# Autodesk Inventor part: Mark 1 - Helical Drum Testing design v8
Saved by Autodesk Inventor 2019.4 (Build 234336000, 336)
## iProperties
Created: 2020-06
Part Number: Mark 1 - Helical Drum Testing design v8
Material: Generic
Document SubType Name: Modeling
Designer: Administrator
Density: 1 g/cm^3
Appearance: Default
Author: Administrator
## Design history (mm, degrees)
feature "Body1"
body "Solid1"
